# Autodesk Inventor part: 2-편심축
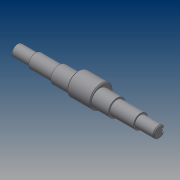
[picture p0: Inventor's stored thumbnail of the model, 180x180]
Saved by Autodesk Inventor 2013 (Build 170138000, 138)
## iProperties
Created: 2014-12
Part Number: 2-편심축
Material: Generic
Document SubType Name: Modeling
Designer: CAD-B16
Density: 1 g/cm^3
Author: CAD-B16
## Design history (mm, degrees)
sketch "스케치1"
  geometry: L1 (-75.5, 0)-(75.5, 0); L2 (-75.5, 0)-(-75.5, 6); L3 (-75.5, 6)-(-55.5, 6); L4 (-55.5, 6)-(-55.5, 7.5); L5 (-55.5, 7.5)-(-30.5, 7.5); L6 (-30.5, 7.5)-(-30.5, 9); L7 (-30.5, 9)-(30.5, 9); L8 (30.5, 9)-(30.5, 7.5); L9 (30.5, 7.5)-(55.5, 7.5); L10 (55.5, 7.5)-(55.5, 6); L11 (55.5, 6)-(75.5, 6); L12 (75.5, 6)-(75.5, 0); L13 (-12.5, 2)-(12.5, 2); L14 (12.5, 2)-(12.5, 14); L15 (12.5, 14)-(-12.5, 14); L16 (-12.5, 14)-(-12.5, 2); 2 further points
  constraints: 32 end point, 10 perpendicular, 5 parallel, 1 coincident, 1 horizontal, 1 midpoint
  dimensions: "d0" = 151 distance of L1.start L1.end; "d2" = 12 diameter of L3 L1; "d3" = 15 diameter of L5 L1; "d4" = 18 diameter of L7 L1; "d5" = 15 diameter of L9 L1; "d6" = 20 distance of L10.end L11.end; "d7" = 12 diameter of L11 L1; "d8" = 25 distance of L8.end L9.end; "d9" = 20 distance of L2.end L3.end; "d10" = 25 distance of L4.end L5.end; "d12" = 2 distance between parallel lines of L1 L13; "d13" = 18 distance between parallel lines of L6 L16; "d14" = 18 distance between parallel lines of L8 L14; "d15" = 24 diameter of L15 L13
revolve "회전1" stored, may be unused: angle "d16" = 90 deg
revolve "회전2" stored, may be unused: angle "d17" = 90 deg
sketch "스케치2"
  geometry: L1 (-75.5, 6)-(-55.5, 6) reference; L2 (-75.5, -6)-(-75.5, 6) reference; L3 (55.5, 6)-(75.5, 6) reference; L4 (75.5, -6)-(75.5, 6) reference; L5 (-75.5, 3)-(-61.5, 3); L6 (-61.5, 3)-(-61.5, 6); L7 (-61.5, 6)-(-75.5, 6); L8 (-75.5, 6)-(-75.5, 3); L9 (61.5, 6)-(75.5, 6); L10 (75.5, 6)-(75.5, 3); L11 (75.5, 3)-(61.5, 3); L12 (61.5, 3)-(61.5, 6); 1 further point
  constraints: 16 end point, 4 parallel, 4 point on line, 2 horizontal, 2 perpendicular
  dimensions: "d18" = 3 distance of L5.end L6.end; "d20" = 14 distance of L5.start L5.end; "d21" = 3 distance of L9.end L10.end; "d22" = 14 distance of L10.end L11.end
extrude "돌출1" cut sketch "스케치2" stored distance "d23" = 5; taper "d24" = 0 deg
fillet "모깎기1" dims "d25" = 2.5
chamfer "모따기1" distance "d26" = 1; stored, may be unused: second distance "d27" = 2, angle "d28" = 45 deg
node "솔리드1"
